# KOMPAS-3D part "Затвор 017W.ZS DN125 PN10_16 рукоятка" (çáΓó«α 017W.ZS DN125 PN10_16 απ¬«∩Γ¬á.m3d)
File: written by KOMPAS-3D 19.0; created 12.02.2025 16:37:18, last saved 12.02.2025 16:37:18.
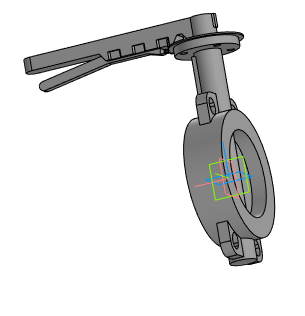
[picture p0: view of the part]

Document properties: Автор: Евгений; Полное имя файла: Затвор 017W.ZS DN125 PN10_16 рукоятка.a3d

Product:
- Part/product: Затвор 017W.ZS DN125 PN10_16 рукоятка
    Масса: 18.1537

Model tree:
1. Операция без истории:1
